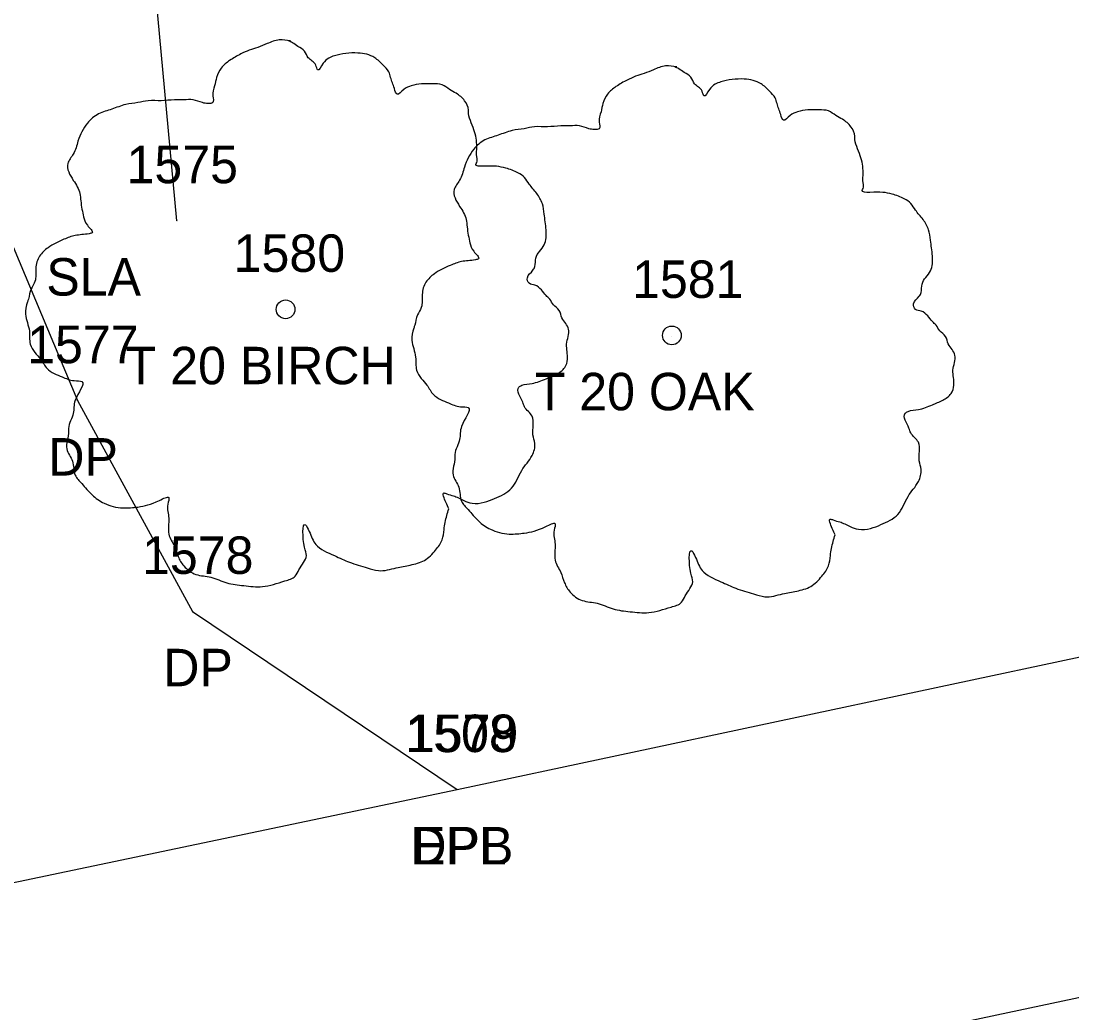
# Model space of a CAD drawing. Extents: x 1965304 to 1970247, y 1117014 to 1118201.
# Drawn here: x 1966592.88 to 1966620.94, y 1117408.09 to 1117434.58 of the extents above; entities that cross this region are included whole.
import ezdxf

# ---------------------------------------------------------------- set-up
doc = ezdxf.new("R2010")
doc.units = 0
for name, color, linetype in [('RD_EX_Driveway', 7, 'Continuous'), ('RD_EX_Driveway_txCode', 7, 'Continuous'), ('RD_EX_Road', 7, 'Continuous'), ('RD_EX_Road_txCode', 7, 'Continuous'), ('RD_EX_VEG', 7, 'Continuous'), ('RD_EX_VEG_txCode', 7, 'Continuous'), ('RD_HC_Cl', 7, 'Continuous'), ('RD_SMD_Locator', 7, 'Continuous')]:
    doc.layers.add(name, color=color, linetype=linetype)

msp = doc.modelspace()

# ---------------------------------------------------------------- linework, layer by layer
at = {"layer": 'RD_EX_Driveway'}
msp.add_lwpolyline([(1966578.388, 1117408.593), (1966578.939, 1117419.648), (1966578.028, 1117435.239), (1966589.341, 1117436.481), (1966594.391, 1117424.44), (1966597.459, 1117418.815), (1966604.527, 1117414.058)], dxfattribs=at)
at = {"layer": 'RD_EX_Road'}
msp.add_lwpolyline([(1966031.823, 1117232.956), (1966074.66, 1117252.15), (1966117.782, 1117271.581), (1966161.06, 1117290.483), (1966205.406, 1117309.226), (1966251.249, 1117327.393), (1966297.245, 1117343.102), (1966344.085, 1117357.038), (1966390.785, 1117368.561), (1966438.122, 1117379.082), (1966484.547, 1117389.131), (1966531.199, 1117398.733), (1966578.388, 1117408.593), (1966604.527, 1117414.058), (1966624.537, 1117418.323), (1966671.319, 1117428.348), (1966716.506, 1117439.32), (1966736.604, 1117445.59), (1966754.133, 1117451.442), (1966759.658, 1117453.517), (1966769.512, 1117457.475)], dxfattribs=at)
at = {"layer": 'RD_EX_VEG'}
msp.add_line((1966597.045, 1117429.245), (1966593.432, 1117467.989), dxfattribs=at)
for centre, radius in [((1966599.944, 1117426.878), 0.25), ((1966599.944, 1117426.878), 0.25), ((1966599.931, 1117426.86), 0.0001), ((1966599.931, 1117426.86), 0.0001), ((1966610.256, 1117426.183), 0.25), ((1966610.256, 1117426.183), 0.25), ((1966610.244, 1117426.164), 0.0001), ((1966610.244, 1117426.164), 0.0001)]:
    msp.add_circle(centre, radius, dxfattribs=at)
for points in [[(1966600.075, 1117434.046), (1966599.776, 1117434.071), (1966599.451, 1117433.971), (1966599.201, 1117433.871), (1966598.976, 1117433.796), (1966598.751, 1117433.696), (1966598.451, 1117433.521), (1966598.226, 1117433.321), (1966598.101, 1117433.071), (1966598.051, 1117432.846), (1966598.001, 1117432.571), (1966598.001, 1117432.396), (1966597.876, 1117432.371), (1966597.726, 1117432.396), (1966597.477, 1117432.471), (1966597.227, 1117432.471), (1966596.977, 1117432.471), (1966596.627, 1117432.446), (1966596.277, 1117432.446), (1966596.002, 1117432.396), (1966595.677, 1117432.346), (1966595.303, 1117432.221), (1966594.953, 1117432.096), (1966594.653, 1117431.847), (1966594.403, 1117431.372), (1966594.278, 1117431.022), (1966594.128, 1117430.772), (1966594.278, 1117430.322), (1966594.453, 1117429.972), (1966594.478, 1117429.772), (1966594.553, 1117429.348), (1966594.653, 1117429.123), (1966594.778, 1117428.923), (1966594.703, 1117428.898), (1966594.328, 1117428.848), (1966594.028, 1117428.748), (1966593.603, 1117428.523), (1966593.378, 1117428.298), (1966593.278, 1117427.973), (1966593.253, 1117427.623), (1966593.154, 1117427.424), (1966593.079, 1117427.149), (1966593.054, 1117427.074), (1966593.004, 1117426.749), (1966593.104, 1117426.299), (1966593.129, 1117425.949), (1966593.253, 1117425.724), (1966593.403, 1117425.549), (1966593.578, 1117425.299), (1966593.978, 1117425.075), (1966594.303, 1117424.975), (1966594.503, 1117424.95), (1966594.328, 1117424.45), (1966594.278, 1117424.1), (1966594.153, 1117423.7), (1966594.153, 1117423.625), (1966594.103, 1117423.15), (1966594.253, 1117422.825), (1966594.328, 1117422.451), (1966594.503, 1117422.226), (1966594.778, 1117421.926), (1966595.103, 1117421.701), (1966595.602, 1117421.576), (1966596.002, 1117421.601), (1966596.577, 1117421.776), (1966596.827, 1117421.851), (1966596.802, 1117421.676), (1966596.827, 1117421.301), (1966596.827, 1117420.876), (1966596.977, 1117420.552), (1966597.077, 1117420.277), (1966597.227, 1117420.027), (1966597.552, 1117419.802), (1966597.951, 1117419.727), (1966598.376, 1117419.577), (1966598.826, 1117419.502), (1966599.326, 1117419.477), (1966599.926, 1117419.627), (1966600.2, 1117419.752), (1966600.3, 1117419.927), (1966600.5, 1117420.302), (1966600.45, 1117420.527), (1966600.475, 1117421.126), (1966600.575, 1117420.951), (1966600.75, 1117420.601), (1966601.25, 1117420.302), (1966601.65, 1117420.127), (1966602.125, 1117419.977), (1966602.424, 1117419.902), (1966602.899, 1117419.977), (1966603.274, 1117420.052), (1966603.649, 1117420.177), (1966603.949, 1117420.452), (1966604.124, 1117420.726), (1966604.174, 1117421.001), (1966604.249, 1117421.376), (1966604.299, 1117421.551)], [(1966600.075, 1117434.046), (1966599.776, 1117434.071), (1966599.451, 1117433.971), (1966599.201, 1117433.871), (1966598.976, 1117433.796), (1966598.751, 1117433.696), (1966598.451, 1117433.521), (1966598.226, 1117433.321), (1966598.101, 1117433.071), (1966598.051, 1117432.846), (1966598.001, 1117432.571), (1966598.001, 1117432.396), (1966597.876, 1117432.371), (1966597.726, 1117432.396), (1966597.477, 1117432.471), (1966597.227, 1117432.471), (1966596.977, 1117432.471), (1966596.627, 1117432.446), (1966596.277, 1117432.446), (1966596.002, 1117432.396), (1966595.677, 1117432.346), (1966595.303, 1117432.221), (1966594.953, 1117432.096), (1966594.653, 1117431.847), (1966594.403, 1117431.372), (1966594.278, 1117431.022), (1966594.128, 1117430.772), (1966594.278, 1117430.322), (1966594.453, 1117429.972), (1966594.478, 1117429.772), (1966594.553, 1117429.348), (1966594.653, 1117429.123), (1966594.778, 1117428.923), (1966594.703, 1117428.898), (1966594.328, 1117428.848), (1966594.028, 1117428.748), (1966593.603, 1117428.523), (1966593.378, 1117428.298), (1966593.278, 1117427.973), (1966593.253, 1117427.623), (1966593.154, 1117427.424), (1966593.079, 1117427.149), (1966593.054, 1117427.074), (1966593.004, 1117426.749), (1966593.104, 1117426.299), (1966593.129, 1117425.949), (1966593.253, 1117425.724), (1966593.403, 1117425.549), (1966593.578, 1117425.299), (1966593.978, 1117425.075), (1966594.303, 1117424.975), (1966594.503, 1117424.95), (1966594.328, 1117424.45), (1966594.278, 1117424.1), (1966594.153, 1117423.7), (1966594.153, 1117423.625), (1966594.103, 1117423.15), (1966594.253, 1117422.825), (1966594.328, 1117422.451), (1966594.503, 1117422.226), (1966594.778, 1117421.926), (1966595.103, 1117421.701), (1966595.602, 1117421.576), (1966596.002, 1117421.601), (1966596.577, 1117421.776), (1966596.827, 1117421.851), (1966596.802, 1117421.676), (1966596.827, 1117421.301), (1966596.827, 1117420.876), (1966596.977, 1117420.552), (1966597.077, 1117420.277), (1966597.227, 1117420.027), (1966597.552, 1117419.802), (1966597.951, 1117419.727), (1966598.376, 1117419.577), (1966598.826, 1117419.502), (1966599.326, 1117419.477), (1966599.926, 1117419.627), (1966600.2, 1117419.752), (1966600.3, 1117419.927), (1966600.5, 1117420.302), (1966600.45, 1117420.527), (1966600.475, 1117421.126), (1966600.575, 1117420.951), (1966600.75, 1117420.601), (1966601.25, 1117420.302), (1966601.65, 1117420.127), (1966602.125, 1117419.977), (1966602.424, 1117419.902), (1966602.899, 1117419.977), (1966603.274, 1117420.052), (1966603.649, 1117420.177), (1966603.949, 1117420.452), (1966604.124, 1117420.726), (1966604.174, 1117421.001), (1966604.249, 1117421.376), (1966604.299, 1117421.551)], [(1966604.299, 1117421.551), (1966604.224, 1117421.726), (1966604.174, 1117421.976), (1966604.249, 1117421.951), (1966604.424, 1117421.901), (1966604.698, 1117421.776), (1966604.923, 1117421.701), (1966605.248, 1117421.726), (1966605.523, 1117421.826), (1966605.973, 1117422.101), (1966606.248, 1117422.576), (1966606.523, 1117422.975), (1966606.598, 1117423.3), (1966606.548, 1117423.525), (1966606.523, 1117424.025), (1966606.323, 1117424.275), (1966606.273, 1117424.4), (1966606.173, 1117424.8), (1966606.248, 1117424.85), (1966606.523, 1117424.9), (1966606.897, 1117425.025), (1966607.172, 1117425.149), (1966607.397, 1117425.324), (1966607.472, 1117425.549), (1966607.447, 1117425.949), (1966607.497, 1117426.349), (1966607.422, 1117426.499), (1966607.322, 1117426.649), (1966607.247, 1117426.849), (1966607.097, 1117426.999), (1966606.997, 1117427.149), (1966606.897, 1117427.249), (1966606.773, 1117427.399), (1966606.598, 1117427.523), (1966606.448, 1117427.573), (1966606.398, 1117427.723), (1966606.548, 1117427.923), (1966606.598, 1117428.023), (1966606.623, 1117428.248), (1966606.848, 1117428.598), (1966606.897, 1117428.998), (1966606.848, 1117429.423), (1966606.798, 1117429.698), (1966606.648, 1117429.972), (1966606.448, 1117430.222), (1966606.323, 1117430.397), (1966606.148, 1117430.522), (1966605.823, 1117430.647), (1966605.573, 1117430.697), (1966605.223, 1117430.697), (1966605.023, 1117430.747), (1966605.048, 1117430.797), (1966605.048, 1117430.947), (1966605.048, 1117431.222), (1966604.973, 1117431.672), (1966604.823, 1117432.171), (1966604.823, 1117432.196), (1966604.723, 1117432.446), (1966604.499, 1117432.646), (1966604.324, 1117432.746), (1966604.124, 1117432.871), (1966603.874, 1117432.896), (1966603.574, 1117432.896), (1966603.299, 1117432.846), (1966603.099, 1117432.746), (1966602.924, 1117432.621), (1966602.849, 1117432.771), (1966602.749, 1117433.071), (1966602.699, 1117433.221), (1966602.549, 1117433.396), (1966602.325, 1117433.596), (1966601.875, 1117433.721), (1966601.25, 1117433.646), (1966600.95, 1117433.446), (1966600.8, 1117433.271), (1966600.75, 1117433.396), (1966600.55, 1117433.596), (1966600.45, 1117433.771), (1966600.275, 1117433.896), (1966600.125, 1117433.996), (1966600.025, 1117434.046)], [(1966604.299, 1117421.551), (1966604.224, 1117421.726), (1966604.174, 1117421.976), (1966604.249, 1117421.951), (1966604.424, 1117421.901), (1966604.698, 1117421.776), (1966604.923, 1117421.701), (1966605.248, 1117421.726), (1966605.523, 1117421.826), (1966605.973, 1117422.101), (1966606.248, 1117422.576), (1966606.523, 1117422.975), (1966606.598, 1117423.3), (1966606.548, 1117423.525), (1966606.523, 1117424.025), (1966606.323, 1117424.275), (1966606.273, 1117424.4), (1966606.173, 1117424.8), (1966606.248, 1117424.85), (1966606.523, 1117424.9), (1966606.897, 1117425.025), (1966607.172, 1117425.149), (1966607.397, 1117425.324), (1966607.472, 1117425.549), (1966607.447, 1117425.949), (1966607.497, 1117426.349), (1966607.422, 1117426.499), (1966607.322, 1117426.649), (1966607.247, 1117426.849), (1966607.097, 1117426.999), (1966606.997, 1117427.149), (1966606.897, 1117427.249), (1966606.773, 1117427.399), (1966606.598, 1117427.523), (1966606.448, 1117427.573), (1966606.398, 1117427.723), (1966606.548, 1117427.923), (1966606.598, 1117428.023), (1966606.623, 1117428.248), (1966606.848, 1117428.598), (1966606.897, 1117428.998), (1966606.848, 1117429.423), (1966606.798, 1117429.698), (1966606.648, 1117429.972), (1966606.448, 1117430.222), (1966606.323, 1117430.397), (1966606.148, 1117430.522), (1966605.823, 1117430.647), (1966605.573, 1117430.697), (1966605.223, 1117430.697), (1966605.023, 1117430.747), (1966605.048, 1117430.797), (1966605.048, 1117430.947), (1966605.048, 1117431.222), (1966604.973, 1117431.672), (1966604.823, 1117432.171), (1966604.823, 1117432.196), (1966604.723, 1117432.446), (1966604.499, 1117432.646), (1966604.324, 1117432.746), (1966604.124, 1117432.871), (1966603.874, 1117432.896), (1966603.574, 1117432.896), (1966603.299, 1117432.846), (1966603.099, 1117432.746), (1966602.924, 1117432.621), (1966602.849, 1117432.771), (1966602.749, 1117433.071), (1966602.699, 1117433.221), (1966602.549, 1117433.396), (1966602.325, 1117433.596), (1966601.875, 1117433.721), (1966601.25, 1117433.646), (1966600.95, 1117433.446), (1966600.8, 1117433.271), (1966600.75, 1117433.396), (1966600.55, 1117433.596), (1966600.45, 1117433.771), (1966600.275, 1117433.896), (1966600.125, 1117433.996), (1966600.025, 1117434.046)], [(1966610.388, 1117433.35), (1966610.088, 1117433.375), (1966609.763, 1117433.275), (1966609.514, 1117433.175), (1966609.289, 1117433.1), (1966609.064, 1117433), (1966608.764, 1117432.825), (1966608.539, 1117432.625), (1966608.414, 1117432.375), (1966608.364, 1117432.151), (1966608.314, 1117431.876), (1966608.314, 1117431.701), (1966608.189, 1117431.676), (1966608.039, 1117431.701), (1966607.789, 1117431.776), (1966607.539, 1117431.776), (1966607.289, 1117431.776), (1966606.94, 1117431.751), (1966606.59, 1117431.751), (1966606.315, 1117431.701), (1966605.99, 1117431.651), (1966605.615, 1117431.526), (1966605.265, 1117431.401), (1966604.966, 1117431.151), (1966604.716, 1117430.676), (1966604.591, 1117430.326), (1966604.441, 1117430.076), (1966604.591, 1117429.627), (1966604.766, 1117429.277), (1966604.791, 1117429.077), (1966604.866, 1117428.652), (1966604.966, 1117428.427), (1966605.09, 1117428.227), (1966605.016, 1117428.202), (1966604.641, 1117428.152), (1966604.341, 1117428.052), (1966603.916, 1117427.827), (1966603.691, 1117427.603), (1966603.591, 1117427.278), (1966603.566, 1117426.928), (1966603.466, 1117426.728), (1966603.391, 1117426.453), (1966603.366, 1117426.378), (1966603.316, 1117426.053), (1966603.416, 1117425.603), (1966603.441, 1117425.254), (1966603.566, 1117425.029), (1966603.716, 1117424.854), (1966603.891, 1117424.604), (1966604.291, 1117424.379), (1966604.616, 1117424.279), (1966604.816, 1117424.254), (1966604.641, 1117423.754), (1966604.591, 1117423.404), (1966604.466, 1117423.005), (1966604.466, 1117422.93), (1966604.416, 1117422.455), (1966604.566, 1117422.13), (1966604.641, 1117421.755), (1966604.816, 1117421.53), (1966605.09, 1117421.23), (1966605.415, 1117421.005), (1966605.915, 1117420.88), (1966606.315, 1117420.905), (1966606.89, 1117421.08), (1966607.14, 1117421.155), (1966607.115, 1117420.98), (1966607.14, 1117420.606), (1966607.14, 1117420.181), (1966607.289, 1117419.856), (1966607.389, 1117419.581), (1966607.539, 1117419.331), (1966607.864, 1117419.106), (1966608.264, 1117419.031), (1966608.689, 1117418.881), (1966609.139, 1117418.806), (1966609.638, 1117418.781), (1966610.238, 1117418.931), (1966610.513, 1117419.056), (1966610.613, 1117419.231), (1966610.813, 1117419.606), (1966610.763, 1117419.831), (1966610.788, 1117420.431), (1966610.888, 1117420.256), (1966611.063, 1117419.906), (1966611.563, 1117419.606), (1966611.962, 1117419.431), (1966612.437, 1117419.281), (1966612.737, 1117419.206), (1966613.212, 1117419.281), (1966613.587, 1117419.356), (1966613.962, 1117419.481), (1966614.261, 1117419.756), (1966614.436, 1117420.031), (1966614.486, 1117420.306), (1966614.561, 1117420.681), (1966614.611, 1117420.855)], [(1966610.388, 1117433.35), (1966610.088, 1117433.375), (1966609.763, 1117433.275), (1966609.514, 1117433.175), (1966609.289, 1117433.1), (1966609.064, 1117433), (1966608.764, 1117432.825), (1966608.539, 1117432.625), (1966608.414, 1117432.375), (1966608.364, 1117432.151), (1966608.314, 1117431.876), (1966608.314, 1117431.701), (1966608.189, 1117431.676), (1966608.039, 1117431.701), (1966607.789, 1117431.776), (1966607.539, 1117431.776), (1966607.289, 1117431.776), (1966606.94, 1117431.751), (1966606.59, 1117431.751), (1966606.315, 1117431.701), (1966605.99, 1117431.651), (1966605.615, 1117431.526), (1966605.265, 1117431.401), (1966604.966, 1117431.151), (1966604.716, 1117430.676), (1966604.591, 1117430.326), (1966604.441, 1117430.076), (1966604.591, 1117429.627), (1966604.766, 1117429.277), (1966604.791, 1117429.077), (1966604.866, 1117428.652), (1966604.966, 1117428.427), (1966605.09, 1117428.227), (1966605.016, 1117428.202), (1966604.641, 1117428.152), (1966604.341, 1117428.052), (1966603.916, 1117427.827), (1966603.691, 1117427.603), (1966603.591, 1117427.278), (1966603.566, 1117426.928), (1966603.466, 1117426.728), (1966603.391, 1117426.453), (1966603.366, 1117426.378), (1966603.316, 1117426.053), (1966603.416, 1117425.603), (1966603.441, 1117425.254), (1966603.566, 1117425.029), (1966603.716, 1117424.854), (1966603.891, 1117424.604), (1966604.291, 1117424.379), (1966604.616, 1117424.279), (1966604.816, 1117424.254), (1966604.641, 1117423.754), (1966604.591, 1117423.404), (1966604.466, 1117423.005), (1966604.466, 1117422.93), (1966604.416, 1117422.455), (1966604.566, 1117422.13), (1966604.641, 1117421.755), (1966604.816, 1117421.53), (1966605.09, 1117421.23), (1966605.415, 1117421.005), (1966605.915, 1117420.88), (1966606.315, 1117420.905), (1966606.89, 1117421.08), (1966607.14, 1117421.155), (1966607.115, 1117420.98), (1966607.14, 1117420.606), (1966607.14, 1117420.181), (1966607.289, 1117419.856), (1966607.389, 1117419.581), (1966607.539, 1117419.331), (1966607.864, 1117419.106), (1966608.264, 1117419.031), (1966608.689, 1117418.881), (1966609.139, 1117418.806), (1966609.638, 1117418.781), (1966610.238, 1117418.931), (1966610.513, 1117419.056), (1966610.613, 1117419.231), (1966610.813, 1117419.606), (1966610.763, 1117419.831), (1966610.788, 1117420.431), (1966610.888, 1117420.256), (1966611.063, 1117419.906), (1966611.563, 1117419.606), (1966611.962, 1117419.431), (1966612.437, 1117419.281), (1966612.737, 1117419.206), (1966613.212, 1117419.281), (1966613.587, 1117419.356), (1966613.962, 1117419.481), (1966614.261, 1117419.756), (1966614.436, 1117420.031), (1966614.486, 1117420.306), (1966614.561, 1117420.681), (1966614.611, 1117420.855)], [(1966614.611, 1117420.855), (1966614.536, 1117421.03), (1966614.486, 1117421.28), (1966614.561, 1117421.255), (1966614.736, 1117421.205), (1966615.011, 1117421.08), (1966615.236, 1117421.005), (1966615.561, 1117421.03), (1966615.836, 1117421.13), (1966616.286, 1117421.405), (1966616.56, 1117421.88), (1966616.835, 1117422.28), (1966616.91, 1117422.605), (1966616.86, 1117422.83), (1966616.835, 1117423.329), (1966616.635, 1117423.579), (1966616.585, 1117423.704), (1966616.485, 1117424.104), (1966616.56, 1117424.154), (1966616.835, 1117424.204), (1966617.21, 1117424.329), (1966617.485, 1117424.454), (1966617.71, 1117424.629), (1966617.785, 1117424.854), (1966617.76, 1117425.254), (1966617.81, 1117425.653), (1966617.735, 1117425.803), (1966617.635, 1117425.953), (1966617.56, 1117426.153), (1966617.41, 1117426.303), (1966617.31, 1117426.453), (1966617.21, 1117426.553), (1966617.085, 1117426.703), (1966616.91, 1117426.828), (1966616.76, 1117426.878), (1966616.71, 1117427.028), (1966616.86, 1117427.228), (1966616.91, 1117427.328), (1966616.935, 1117427.553), (1966617.16, 1117427.902), (1966617.21, 1117428.302), (1966617.16, 1117428.727), (1966617.11, 1117429.002), (1966616.96, 1117429.277), (1966616.76, 1117429.527), (1966616.635, 1117429.702), (1966616.46, 1117429.827), (1966616.136, 1117429.952), (1966615.886, 1117430.001), (1966615.536, 1117430.001), (1966615.336, 1117430.051), (1966615.361, 1117430.101), (1966615.361, 1117430.251), (1966615.361, 1117430.526), (1966615.286, 1117430.976), (1966615.136, 1117431.476), (1966615.136, 1117431.501), (1966615.036, 1117431.751), (1966614.811, 1117431.951), (1966614.636, 1117432.051), (1966614.436, 1117432.176), (1966614.186, 1117432.201), (1966613.887, 1117432.201), (1966613.612, 1117432.151), (1966613.412, 1117432.051), (1966613.237, 1117431.926), (1966613.162, 1117432.076), (1966613.062, 1117432.375), (1966613.012, 1117432.525), (1966612.862, 1117432.7), (1966612.637, 1117432.9), (1966612.187, 1117433.025), (1966611.563, 1117432.95), (1966611.263, 1117432.75), (1966611.113, 1117432.575), (1966611.063, 1117432.7), (1966610.863, 1117432.9), (1966610.763, 1117433.075), (1966610.588, 1117433.2), (1966610.438, 1117433.3), (1966610.338, 1117433.35)], [(1966614.611, 1117420.855), (1966614.536, 1117421.03), (1966614.486, 1117421.28), (1966614.561, 1117421.255), (1966614.736, 1117421.205), (1966615.011, 1117421.08), (1966615.236, 1117421.005), (1966615.561, 1117421.03), (1966615.836, 1117421.13), (1966616.286, 1117421.405), (1966616.56, 1117421.88), (1966616.835, 1117422.28), (1966616.91, 1117422.605), (1966616.86, 1117422.83), (1966616.835, 1117423.329), (1966616.635, 1117423.579), (1966616.585, 1117423.704), (1966616.485, 1117424.104), (1966616.56, 1117424.154), (1966616.835, 1117424.204), (1966617.21, 1117424.329), (1966617.485, 1117424.454), (1966617.71, 1117424.629), (1966617.785, 1117424.854), (1966617.76, 1117425.254), (1966617.81, 1117425.653), (1966617.735, 1117425.803), (1966617.635, 1117425.953), (1966617.56, 1117426.153), (1966617.41, 1117426.303), (1966617.31, 1117426.453), (1966617.21, 1117426.553), (1966617.085, 1117426.703), (1966616.91, 1117426.828), (1966616.76, 1117426.878), (1966616.71, 1117427.028), (1966616.86, 1117427.228), (1966616.91, 1117427.328), (1966616.935, 1117427.553), (1966617.16, 1117427.902), (1966617.21, 1117428.302), (1966617.16, 1117428.727), (1966617.11, 1117429.002), (1966616.96, 1117429.277), (1966616.76, 1117429.527), (1966616.635, 1117429.702), (1966616.46, 1117429.827), (1966616.136, 1117429.952), (1966615.886, 1117430.001), (1966615.536, 1117430.001), (1966615.336, 1117430.051), (1966615.361, 1117430.101), (1966615.361, 1117430.251), (1966615.361, 1117430.526), (1966615.286, 1117430.976), (1966615.136, 1117431.476), (1966615.136, 1117431.501), (1966615.036, 1117431.751), (1966614.811, 1117431.951), (1966614.636, 1117432.051), (1966614.436, 1117432.176), (1966614.186, 1117432.201), (1966613.887, 1117432.201), (1966613.612, 1117432.151), (1966613.412, 1117432.051), (1966613.237, 1117431.926), (1966613.162, 1117432.076), (1966613.062, 1117432.375), (1966613.012, 1117432.525), (1966612.862, 1117432.7), (1966612.637, 1117432.9), (1966612.187, 1117433.025), (1966611.563, 1117432.95), (1966611.263, 1117432.75), (1966611.113, 1117432.575), (1966611.063, 1117432.7), (1966610.863, 1117432.9), (1966610.763, 1117433.075), (1966610.588, 1117433.2), (1966610.438, 1117433.3), (1966610.338, 1117433.35)]]:
    msp.add_spline(points, degree=3, dxfattribs=at)
at = {"layer": 'RD_HC_Cl'}
msp.add_line((1966425.261, 1117367.215), (1966684.871, 1117421.945), dxfattribs=at)
at = {"layer": 'RD_SMD_Locator'}
for centre in [(1966597.045, 1117429.245), (1966597.045, 1117429.245), (1966594.391, 1117424.44), (1966594.391, 1117424.44), (1966597.459, 1117418.815), (1966597.459, 1117418.815), (1966604.527, 1117414.058), (1966604.527, 1117414.058), (1966604.527, 1117414.058), (1966604.527, 1117414.058)]:
    msp.add_circle(centre, 0.001, dxfattribs=at)

# ---------------------------------------------------------------- texts
at = {"layer": 'RD_EX_Driveway_txCode'}
for s, p in [('1577', (1966593.045, 1117425.44)), ('1577', (1966593.045, 1117425.44)), ('DP', (1966593.612, 1117422.44)), ('DP', (1966593.612, 1117422.44)), ('1578', (1966596.112, 1117419.815)), ('1578', (1966596.112, 1117419.815)), ('DP', (1966596.679, 1117416.815)), ('DP', (1966596.679, 1117416.815)), ('1579', (1966603.181, 1117415.058)), ('1579', (1966603.181, 1117415.058)), ('DPB', (1966603.275, 1117412.058)), ('DPB', (1966603.275, 1117412.058))]:
    msp.add_text(s, height=1, dxfattribs=at).set_placement(p)
at = {"layer": 'RD_EX_Road_txCode'}
for s, p in [('1508', (1966603.141, 1117415.058)), ('1508', (1966603.141, 1117415.058)), ('EPL', (1966603.322, 1117412.058)), ('EPL', (1966603.322, 1117412.058))]:
    msp.add_text(s, height=1, dxfattribs=at).set_placement(p)
at = {"layer": 'RD_EX_VEG_txCode'}
for s, p in [('1575', (1966595.699, 1117430.245)), ('1575', (1966595.699, 1117430.245)), ('1580', (1966598.558, 1117427.878)), ('1580', (1966598.558, 1117427.878)), ('SLA', (1966593.557, 1117427.245)), ('SLA', (1966593.557, 1117427.245)), ('1581', (1966609.193, 1117427.183)), ('1581', (1966609.193, 1117427.183)), ('T 20 BIRCH', (1966595.676, 1117424.878)), ('T 20 BIRCH', (1966595.676, 1117424.878)), ('T 20 OAK', (1966606.595, 1117424.183)), ('T 20 OAK', (1966606.595, 1117424.183))]:
    msp.add_text(s, height=1, dxfattribs=at).set_placement(p)

doc.saveas('drawing.dxf')
